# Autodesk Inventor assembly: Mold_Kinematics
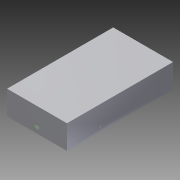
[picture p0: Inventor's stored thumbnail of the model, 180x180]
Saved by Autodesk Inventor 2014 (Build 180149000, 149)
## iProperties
Created: 2009-12
Part Number: Mold_Kinematics
Document SubType Name: Assembly
Designer: gaom
Author: gaom
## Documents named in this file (2)
- C:\Users\iTools\Desktop\tutorial files\Mold\Mold Kinematics\Mold_Kinematics.iam
- C:\Users\iTools\Desktop\tutorial files\Mold\Mold Kinematics\Mold_Kinematics_cover_speaker_LY.iam
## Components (1 placed, 1 different names)
1. Mold_Kinematics_cover_speaker_LY:1 [sub-assembly] — Flush:1, Flush:2, Flush:3
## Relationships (3: Flush 3)
- Flush:1: Mold_Kinematics_cover_speaker_LY:1
- Flush:2: Mold_Kinematics_cover_speaker_LY:1
- Flush:3: Mold_Kinematics_cover_speaker_LY:1
